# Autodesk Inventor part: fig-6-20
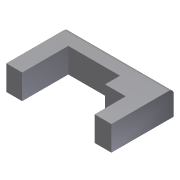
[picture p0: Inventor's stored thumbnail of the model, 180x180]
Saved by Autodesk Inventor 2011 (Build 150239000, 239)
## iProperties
Created: 2010-08
Part Number: fig-6-20
Document SubType Name: Modeling
Designer: CADSoft
Density: 1 g/cm^3
Author: CADSoft
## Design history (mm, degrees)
sketch "Sketch1"
  geometry: L1 (-25.394, 25.152)-(17.03, 25.152); L2 (17.03, 25.152)-(17.03, 0); L3 (-25.394, 0)-(-25.394, 25.152); L4 (10.242, 0)-(10.242, 12.576); L5 (10.242, 12.576)-(1.879, 12.576); L6 (1.879, 12.576)-(1.879, 18.606); L7 (1.879, 18.606)-(-18.97, 18.606); L8 (-18.97, 18.606)-(-18.97, 0); L9 (17.03, 0)-(10.242, 0); L10 (-18.97, 0)-(-25.394, 0); 1 further point
  constraints: 20 end point, 6 parallel, 4 perpendicular, 1 horizontal
extrude "Extrusion1" new body sketch "Sketch1" distance "d0" = 10; taper "d1" = 0 deg
fillet "Fillet1" dims "d2" = 2
body "Solid1"
